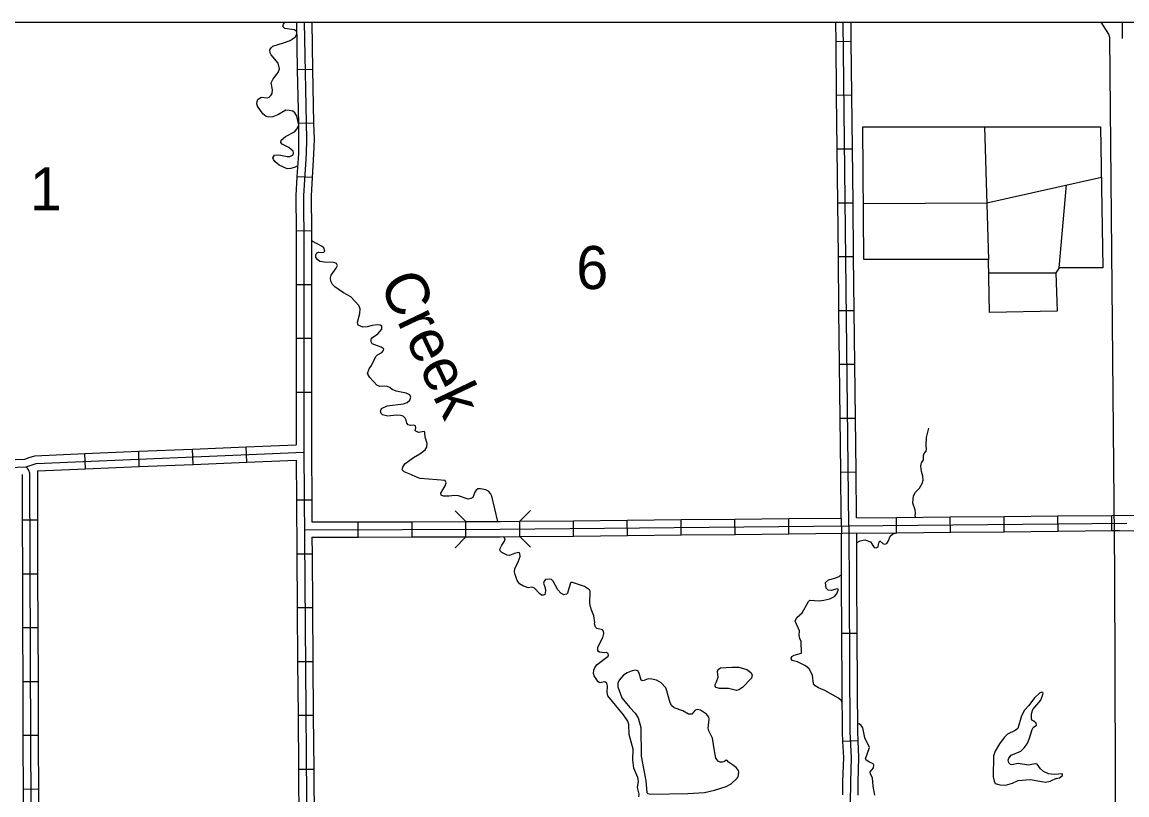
# Model space of a CAD drawing. Extents: x 982240 to 1103002, y 974866 to 1054902.
# Drawn here: x 1046772 to 1057609, y 1010471 to 1018049 of the extents above; entities that cross this region are included whole.
import ezdxf

# ---------------------------------------------------------------- set-up
doc = ezdxf.new("R2010")
doc.units = 0
for name, color, linetype in [('10', 7, 'Continuous'), ('32', 7, 'Continuous'), ('35', 7, 'Continuous'), ('38', 7, 'Continuous'), ('45', 7, 'Continuous'), ('5', 7, 'Continuous'), ('R_Draft', 7, 'Continuous')]:
    doc.layers.add(name, color=color, linetype=linetype)

msp = doc.modelspace()

# ---------------------------------------------------------------- linework, layer by layer
at = {"layer": '10'}
msp.add_lwpolyline([(1057522, 1006715), (1057508, 1007730), (1057491, 1012652), (1057441, 1017898), (1057431, 1017930), (1057357, 1018049)], dxfattribs=at)
at = {"layer": '32'}
for p, q in [((1054756, 1017860), (1054754, 1018049)), ((1054906, 1017862), (1054904, 1018049)), ((1054756, 1017860), (1054906, 1017862)), ((1049622, 1017585), (1049472, 1017582)), ((1054761, 1017332), (1054911, 1017334)), ((1049632, 1017057), (1049482, 1017054)), ((1054767, 1016805), (1054917, 1016806)), ((1049618, 1016524), (1049468, 1016533)), ((1054773, 1016277), (1054923, 1016278)), ((1049610, 1016001), (1049460, 1016000)), ((1054779, 1015749), (1054929, 1015750)), ((1049611, 1015473), (1049461, 1015473)), ((1054785, 1015221), (1054935, 1015222)), ((1049611, 1014945), (1049461, 1014945)), ((1054791, 1014693), (1054941, 1014694)), ((1049610, 1014417), (1049460, 1014417)), ((1049460, 1014417), (1049460, 1013905)), ((1054796, 1014165), (1054946, 1014166)), ((1048971, 1013884), (1049460, 1013905)), ((1047395, 1013668), (1047389, 1013818)), ((1047922, 1013690), (1047916, 1013840)), ((1048450, 1013712), (1048444, 1013862)), ((1048978, 1013734), (1048971, 1013884)), ((1048978, 1013734), (1049461, 1013754)), ((1049461, 1013754), (1049463, 1013360)), ((1046772, 1013612), (1046773, 1013168)), ((1046922, 1013648), (1047395, 1013668)), ((1046922, 1013648), (1046923, 1013168)), ((1054802, 1013637), (1054952, 1013638)), ((1054807, 1013186), (1054802, 1013637)), ((1054957, 1013187), (1054952, 1013638)), ((1049613, 1013361), (1049463, 1013360)), ((1046773, 1013168), (1046923, 1013168)), ((1050070, 1012999), (1050069, 1013149)), ((1050598, 1013000), (1050597, 1013150)), ((1051126, 1013001), (1051125, 1013151)), ((1051654, 1013004), (1051653, 1013154)), ((1052182, 1013009), (1052181, 1013159)), ((1052710, 1013015), (1052709, 1013165)), ((1053238, 1013020), (1053237, 1013170)), ((1053766, 1013025), (1053765, 1013175)), ((1054293, 1013180), (1054807, 1013186)), ((1054294, 1013030), (1054293, 1013180)), ((1054813, 1013030), (1054811, 1013180)), ((1054957, 1013187), (1055349, 1013191)), ((1055350, 1013041), (1055349, 1013191)), ((1055878, 1013046), (1055877, 1013196)), ((1056406, 1013051), (1056405, 1013201)), ((1056934, 1013057), (1056933, 1013207)), ((1057462, 1013062), (1057461, 1013212)), ((1049617, 1012833), (1049467, 1012832)), ((1046775, 1012640), (1046925, 1012640)), ((1049621, 1012305), (1049471, 1012304)), ((1046777, 1012112), (1046927, 1012112)), ((1049625, 1011777), (1049475, 1011776)), ((1046779, 1011584), (1046929, 1011584)), ((1049629, 1011249), (1049479, 1011248)), ((1046781, 1011056), (1046931, 1011056)), ((1049633, 1010721), (1049483, 1010720)), ((1046784, 1010528), (1046934, 1010529))]:
    msp.add_line(p, q, dxfattribs=at)
for points in [[(1049463, 1018049), (1049472, 1017582)], [(1049540, 1018049), (1049562, 1016898), (1049558, 1016757), (1049533, 1016348), (1049537, 1015835), (1049536, 1013831), (1049577, 1008327), (1049592, 1007765), (1049585, 1007779), (1049616, 1001142)], [(1049613, 1018049), (1049622, 1017585)], [(1054882, 1013110), (1054827, 1018049)], [(1057567, 1017887), (1057565, 1018049)], [(1054761, 1017332), (1054756, 1017860)], [(1054911, 1017334), (1054906, 1017862)], [(1049472, 1017582), (1049482, 1017054)], [(1049622, 1017585), (1049632, 1017057)], [(1054767, 1016805), (1054761, 1017332)], [(1054917, 1016806), (1054911, 1017334)], [(1049482, 1017054), (1049485, 1016899), (1049482, 1016760), (1049468, 1016533)], [(1049632, 1017057), (1049636, 1016898), (1049632, 1016753), (1049618, 1016524)], [(1054773, 1016277), (1054767, 1016805)], [(1054923, 1016278), (1054917, 1016806)], [(1049468, 1016533), (1049457, 1016350), (1049460, 1016000)], [(1049618, 1016524), (1049607, 1016346), (1049610, 1016001)], [(1054779, 1015749), (1054773, 1016277)], [(1054929, 1015750), (1054923, 1016278)], [(1049460, 1016000), (1049461, 1015835), (1049461, 1015473)], [(1049610, 1016001), (1049611, 1015835), (1049611, 1015473)], [(1054785, 1015221), (1054779, 1015749)], [(1054935, 1015222), (1054929, 1015750)], [(1049461, 1015473), (1049461, 1014945)], [(1049611, 1015473), (1049611, 1014945)], [(1054791, 1014693), (1054785, 1015221)], [(1054941, 1014694), (1054935, 1015222)], [(1049461, 1014945), (1049460, 1014417)], [(1049611, 1014945), (1049610, 1014417)], [(1054796, 1014165), (1054791, 1014693)], [(1054946, 1014166), (1054941, 1014694)], [(1049610, 1014417), (1049610, 1013889)], [(1054802, 1013637), (1054796, 1014165)], [(1054952, 1013638), (1054946, 1014166)], [(1044148, 1013587), (1046814, 1013688), (1046911, 1013721), (1049536, 1013831)], [(1046842, 1013778), (1046897, 1013797), (1047389, 1013818)], [(1047389, 1013818), (1047916, 1013840)], [(1047916, 1013840), (1048444, 1013862)], [(1048444, 1013862), (1048971, 1013884)], [(1049610, 1013889), (1049610, 1013832), (1049613, 1013361)], [(1046339, 1013746), (1046800, 1013764), (1046842, 1013778)], [(1046814, 1013688), (1046836, 1013656), (1046845, 1013628), (1046855, 1010971), (1046871, 1008241)], [(1047395, 1013668), (1047922, 1013690)], [(1047922, 1013690), (1048450, 1013712)], [(1048450, 1013712), (1048978, 1013734)], [(1049463, 1013360), (1049467, 1012832)], [(1049613, 1013361), (1049615, 1013148)], [(1046773, 1013168), (1046775, 1012640)], [(1046923, 1013168), (1046925, 1012640)], [(1049542, 1013071), (1051463, 1013076), (1057609, 1013137)], [(1049615, 1013148), (1050069, 1013149)], [(1050069, 1013149), (1050597, 1013150)], [(1050597, 1013150), (1051125, 1013151)], [(1051125, 1013151), (1051462, 1013152), (1051653, 1013154)], [(1051653, 1013154), (1052181, 1013159)], [(1052181, 1013159), (1052709, 1013165)], [(1052709, 1013165), (1053237, 1013170)], [(1053237, 1013170), (1053765, 1013175)], [(1053765, 1013175), (1054293, 1013180)], [(1055349, 1013191), (1055877, 1013196)], [(1055877, 1013196), (1056405, 1013201)], [(1056405, 1013201), (1056933, 1013207)], [(1056933, 1013207), (1057461, 1013212)], [(1057461, 1013212), (1057685, 1013214), (1057972, 1013210)], [(1053238, 1013020), (1053766, 1013025)], [(1053766, 1013025), (1054294, 1013030)], [(1054294, 1013030), (1054822, 1013036)], [(1054822, 1013036), (1055350, 1013041)], [(1055350, 1013041), (1055878, 1013046)], [(1055878, 1013046), (1056406, 1013051)], [(1056406, 1013051), (1056934, 1013057)], [(1056934, 1013057), (1057462, 1013062)], [(1057462, 1013062), (1057536, 1013063), (1057977, 1013060)], [(1049616, 1012998), (1050070, 1012999)], [(1049616, 1012998), (1049617, 1012833)], [(1050070, 1012999), (1050598, 1013000)], [(1050598, 1013000), (1051126, 1013001)], [(1051126, 1013001), (1051463, 1013002), (1051654, 1013004)], [(1051654, 1013004), (1052182, 1013009)], [(1052182, 1013009), (1052710, 1013015)], [(1052710, 1013015), (1053238, 1013020)], [(1049467, 1012832), (1049471, 1012304)], [(1049617, 1012833), (1049621, 1012305)], [(1046775, 1012640), (1046777, 1012112)], [(1046925, 1012640), (1046927, 1012112)], [(1049471, 1012304), (1049475, 1011776)], [(1049621, 1012305), (1049625, 1011777)], [(1046777, 1012112), (1046779, 1011584)], [(1046927, 1012112), (1046929, 1011584)], [(1049475, 1011776), (1049479, 1011248)], [(1049625, 1011777), (1049629, 1011249)], [(1046779, 1011584), (1046781, 1011056)], [(1046929, 1011584), (1046931, 1011056)], [(1049479, 1011248), (1049483, 1010720)], [(1049629, 1011249), (1049633, 1010721)], [(1046781, 1011056), (1046781, 1010970), (1046784, 1010528)], [(1046931, 1011056), (1046931, 1010971), (1046934, 1010529)], [(1049483, 1010720), (1049487, 1010192)], [(1049633, 1010721), (1049637, 1010193)], [(1046784, 1010528), (1046787, 1010000)], [(1046934, 1010529), (1046937, 1010001)]]:
    msp.add_lwpolyline(points, dxfattribs=at)
at = {"layer": '35'}
for points in [[(1049466, 1017956), (1049441, 1017974), (1049350, 1017986), (1049330, 1018005), (1049335, 1018030), (1049351, 1018049)], [(1049214, 1017798), (1049231, 1017814), (1049336, 1017844), (1049403, 1017869), (1049452, 1017902), (1049467, 1017930)], [(1049473, 1016640), (1049451, 1016626), (1049410, 1016613), (1049371, 1016611), (1049293, 1016645), (1049255, 1016678), (1049239, 1016701), (1049233, 1016718), (1049248, 1016743), (1049291, 1016747), (1049372, 1016732), (1049400, 1016732), (1049430, 1016747), (1049434, 1016764), (1049430, 1016783), (1049413, 1016801), (1049388, 1016818), (1049322, 1016851), (1049309, 1016869), (1049314, 1016892), (1049355, 1016926), (1049443, 1016974), (1049463, 1016997), (1049486, 1017039), (1049474, 1017100), (1049464, 1017132), (1049449, 1017160), (1049427, 1017174), (1049393, 1017182), (1049360, 1017184), (1049282, 1017139), (1049231, 1017120), (1049191, 1017116), (1049165, 1017124), (1049134, 1017148), (1049081, 1017223), (1049074, 1017247), (1049077, 1017271), (1049085, 1017290), (1049118, 1017313), (1049178, 1017307), (1049195, 1017313), (1049212, 1017328), (1049226, 1017349), (1049228, 1017383), (1049217, 1017454), (1049235, 1017494), (1049284, 1017556), (1049297, 1017589), (1049284, 1017646), (1049214, 1017727), (1049206, 1017748), (1049204, 1017778), (1049214, 1017798)], [(1055019, 1017023), (1057351, 1017023)], [(1055029, 1015720), (1055019, 1017023)], [(1056211, 1017023), (1056253, 1015720)], [(1057351, 1017023), (1057372, 1015640)], [(1055024, 1016271), (1056235, 1016275), (1057359, 1016529)], [(1056946, 1015640), (1057018, 1016452)], [(1049796, 1015542), (1049805, 1015568), (1049854, 1015635), (1049865, 1015661), (1049857, 1015682), (1049831, 1015692), (1049738, 1015695), (1049692, 1015702), (1049672, 1015717), (1049655, 1015742), (1049653, 1015765), (1049664, 1015787), (1049683, 1015793), (1049716, 1015789), (1049732, 1015792), (1049742, 1015803), (1049733, 1015834), (1049716, 1015847), (1049618, 1015899), (1049608, 1015907)], [(1057372, 1015640), (1056946, 1015640), (1056913, 1015589), (1056925, 1015215), (1056261, 1015202), (1056253, 1015720), (1055029, 1015720)], [(1050881, 1013430), (1050922, 1013503), (1050932, 1013532), (1050921, 1013554), (1050676, 1013575), (1050642, 1013587), (1050585, 1013612), (1050519, 1013640), (1050502, 1013660), (1050506, 1013685), (1050528, 1013717), (1050612, 1013779), (1050675, 1013815), (1050726, 1013853), (1050741, 1013881), (1050745, 1013915), (1050725, 1013978), (1050724, 1014028), (1050715, 1014034), (1050661, 1014023), (1050627, 1014041), (1050634, 1014070), (1050632, 1014091), (1050610, 1014098), (1050582, 1014094), (1050558, 1014100), (1050545, 1014116), (1050539, 1014146), (1050529, 1014165), (1050511, 1014183), (1050484, 1014192), (1050442, 1014193), (1050359, 1014183), (1050307, 1014197), (1050293, 1014212), (1050287, 1014234), (1050297, 1014259), (1050353, 1014285), (1050514, 1014305), (1050548, 1014320), (1050577, 1014342), (1050585, 1014370), (1050577, 1014393), (1050540, 1014409), (1050440, 1014429), (1050401, 1014446), (1050379, 1014467), (1050347, 1014480), (1050282, 1014474), (1050252, 1014490), (1050183, 1014563), (1050162, 1014603), (1050177, 1014649), (1050200, 1014681), (1050242, 1014769), (1050259, 1014787), (1050302, 1014809), (1050314, 1014824), (1050319, 1014840), (1050312, 1014852), (1050296, 1014862), (1050205, 1014894), (1050195, 1014912), (1050196, 1014939), (1050210, 1014957), (1050262, 1014993), (1050302, 1015038), (1050301, 1015066), (1050284, 1015078), (1050256, 1015080), (1050206, 1015074), (1050156, 1015059), (1050114, 1015058), (1050068, 1015078), (1050063, 1015107), (1050085, 1015191), (1050089, 1015237), (1050075, 1015270), (1049996, 1015355), (1049926, 1015393), (1049841, 1015454), (1049817, 1015477), (1049801, 1015508), (1049796, 1015542)], [(1056255, 1015589), (1056913, 1015589)], [(1055587, 1013694), (1055595, 1013726), (1055614, 1013757), (1055615, 1013799), (1055621, 1013819), (1055639, 1013840), (1055643, 1013863), (1055640, 1013895), (1055645, 1013975), (1055666, 1014066)], [(1055535, 1013195), (1055533, 1013209), (1055537, 1013233), (1055533, 1013267), (1055510, 1013331), (1055517, 1013402), (1055536, 1013439), (1055574, 1013480), (1055601, 1013524), (1055610, 1013557), (1055608, 1013596), (1055594, 1013643), (1055587, 1013694)], [(1051440, 1013152), (1051381, 1013400), (1051368, 1013427), (1051346, 1013450), (1051320, 1013461), (1051268, 1013473), (1051244, 1013471), (1051225, 1013459), (1051213, 1013440), (1051192, 1013388), (1051174, 1013377), (1051147, 1013372), (1051053, 1013403), (1051015, 1013408), (1050961, 1013400), (1050905, 1013401), (1050884, 1013410), (1050881, 1013430)], [(1054956, 1012942), (1054992, 1012963), (1055040, 1012972), (1055094, 1012953), (1055130, 1012897), (1055149, 1012894), (1055170, 1012904), (1055176, 1012943), (1055185, 1012962), (1055214, 1012936), (1055232, 1012928), (1055255, 1012937), (1055272, 1012962), (1055288, 1013007), (1055313, 1013030), (1055353, 1013040)], [(1052523, 1011840), (1052520, 1011855), (1052506, 1011866), (1052481, 1011863), (1052437, 1011869), (1052419, 1011880), (1052420, 1011918), (1052469, 1012015), (1052480, 1012055), (1052476, 1012075), (1052467, 1012090), (1052409, 1012101), (1052397, 1012114), (1052388, 1012147), (1052390, 1012162), (1052379, 1012228), (1052353, 1012291), (1052342, 1012349), (1052345, 1012468), (1052338, 1012483), (1052289, 1012513), (1052172, 1012555), (1052159, 1012555), (1052153, 1012549), (1052123, 1012449), (1052111, 1012439), (1052087, 1012433), (1052056, 1012448), (1052028, 1012482), (1051982, 1012567), (1051965, 1012582), (1051942, 1012587), (1051905, 1012582), (1051893, 1012568), (1051886, 1012548), (1051904, 1012500), (1051908, 1012471), (1051900, 1012433), (1051887, 1012428), (1051868, 1012430), (1051851, 1012441), (1051800, 1012499), (1051771, 1012507), (1051737, 1012502), (1051685, 1012520), (1051651, 1012542), (1051629, 1012573), (1051608, 1012633), (1051603, 1012659), (1051604, 1012686), (1051639, 1012755), (1051658, 1012807), (1051655, 1012840), (1051642, 1012849), (1051603, 1012839), (1051552, 1012818), (1051530, 1012821), (1051477, 1012848), (1051461, 1012865), (1051458, 1012880), (1051477, 1012921), (1051505, 1012960), (1051510, 1012981), (1051499, 1013002)], [(1054551, 1011539), (1054536, 1011560), (1054525, 1011646), (1054491, 1011707), (1054456, 1011736), (1054378, 1011775), (1054326, 1011789), (1054317, 1011804), (1054321, 1011828), (1054345, 1011842), (1054418, 1011862), (1054414, 1011975), (1054401, 1012004), (1054396, 1012034), (1054398, 1012080), (1054355, 1012175), (1054373, 1012210), (1054423, 1012256), (1054485, 1012366), (1054498, 1012380), (1054590, 1012374), (1054637, 1012379), (1054695, 1012393), (1054740, 1012415), (1054761, 1012438), (1054780, 1012485), (1054768, 1012492), (1054707, 1012476), (1054678, 1012479), (1054659, 1012498), (1054654, 1012554), (1054681, 1012580), (1054745, 1012595), (1054786, 1012612), (1054799, 1012625)], [(1052822, 1010451), (1052824, 1010478), (1052808, 1010544), (1052817, 1010606), (1052813, 1010643), (1052774, 1010734), (1052762, 1010811), (1052765, 1010918), (1052727, 1011063), (1052725, 1011160), (1052715, 1011193), (1052671, 1011256), (1052518, 1011443), (1052512, 1011476), (1052516, 1011541), (1052509, 1011567), (1052490, 1011580), (1052438, 1011570), (1052422, 1011580), (1052385, 1011638), (1052378, 1011662), (1052380, 1011694), (1052391, 1011719), (1052414, 1011749), (1052521, 1011832), (1052523, 1011840)], [(1053863, 1011548), (1053839, 1011525), (1053803, 1011500), (1053781, 1011496), (1053703, 1011514), (1053614, 1011515), (1053582, 1011523), (1053569, 1011537), (1053569, 1011552), (1053583, 1011579), (1053600, 1011625), (1053595, 1011680), (1053600, 1011701), (1053623, 1011717), (1053735, 1011725), (1053803, 1011722), (1053882, 1011701), (1053920, 1011671), (1053932, 1011647), (1053927, 1011616), (1053901, 1011589)], [(1053700, 1010791), (1053689, 1010808), (1053677, 1010811), (1053661, 1010798), (1053639, 1010792), (1053619, 1010792), (1053600, 1010803), (1053576, 1010832), (1053564, 1010902), (1053544, 1011026), (1053509, 1011100), (1053503, 1011124), (1053513, 1011214), (1053509, 1011232), (1053485, 1011264), (1053428, 1011301), (1053397, 1011309), (1053375, 1011302), (1053342, 1011261), (1053309, 1011262), (1053253, 1011294), (1053169, 1011324), (1053147, 1011343), (1053129, 1011373), (1053097, 1011491), (1053088, 1011521), (1053041, 1011569), (1052996, 1011596), (1052951, 1011606), (1052912, 1011608), (1052863, 1011591), (1052845, 1011596), (1052825, 1011665), (1052811, 1011687), (1052788, 1011693), (1052756, 1011689), (1052706, 1011668), (1052671, 1011644), (1052629, 1011597), (1052616, 1011566), (1052616, 1011529), (1052654, 1011422), (1052732, 1011328), (1052786, 1011273), (1052815, 1011225), (1052841, 1011133), (1052844, 1010851), (1052892, 1010610), (1052899, 1010494), (1052910, 1010484), (1052938, 1010478)], [(1053901, 1011589), (1053863, 1011548)], [(1054814, 1011383), (1054806, 1011397), (1054781, 1011418), (1054645, 1011496), (1054585, 1011520), (1054551, 1011539)], [(1056916, 1010631), (1056949, 1010639), (1056979, 1010661), (1056977, 1010676), (1056899, 1010672), (1056840, 1010679), (1056792, 1010701), (1056762, 1010727), (1056730, 1010771), (1056709, 1010777), (1056644, 1010762), (1056544, 1010778), (1056479, 1010765), (1056466, 1010770), (1056451, 1010786), (1056446, 1010811), (1056452, 1010832), (1056475, 1010860), (1056569, 1010900), (1056603, 1010932), (1056631, 1010973), (1056651, 1011017), (1056681, 1011111), (1056691, 1011132), (1056723, 1011156), (1056719, 1011174), (1056697, 1011194), (1056682, 1011200), (1056673, 1011213), (1056674, 1011267), (1056687, 1011307), (1056765, 1011400), (1056785, 1011456), (1056787, 1011469), (1056784, 1011476), (1056772, 1011477), (1056752, 1011470), (1056702, 1011422), (1056646, 1011346), (1056604, 1011301), (1056575, 1011246), (1056541, 1011122), (1056512, 1011101), (1056438, 1011065), (1056404, 1011035), (1056358, 1010973), (1056318, 1010900), (1056300, 1010855), (1056298, 1010649), (1056307, 1010604), (1056318, 1010582), (1056363, 1010569), (1056417, 1010566), (1056488, 1010587), (1056542, 1010613), (1056661, 1010623), (1056754, 1010605), (1056806, 1010595)], [(1055136, 1010467), (1055121, 1010555), (1055114, 1010638), (1055094, 1010674), (1055092, 1010696), (1055124, 1010737), (1055127, 1010761), (1055121, 1010776), (1055084, 1010792), (1055053, 1010813), (1055046, 1010826), (1055086, 1010937), (1055038, 1011031), (1055018, 1011129), (1055004, 1011153), (1054983, 1011167), (1054968, 1011165)], [(1052938, 1010478), (1053303, 1010484), (1053465, 1010495), (1053565, 1010516), (1053678, 1010553), (1053726, 1010580), (1053788, 1010636), (1053795, 1010649), (1053803, 1010694), (1053798, 1010711), (1053776, 1010740), (1053752, 1010759), (1053700, 1010791)], [(1056806, 1010595), (1056859, 1010607)], [(1056916, 1010631), (1056859, 1010607)]]:
    msp.add_lwpolyline(points, dxfattribs=at)
at = {"layer": '38'}
for points in [[(1051019, 1013257), (1051125, 1013151)], [(1051653, 1013154), (1051758, 1013261)], [(1051126, 1013001), (1051021, 1012895)], [(1051760, 1012899), (1051654, 1013004)]]:
    msp.add_lwpolyline(points, dxfattribs=at)
at = {"layer": '45'}
for p, q in [((1054806, 1013036), (1054808, 1012581)), ((1054956, 1013037), (1054958, 1012582)), ((1054961, 1012054), (1054811, 1012053)), ((1054970, 1011001), (1054820, 1010994))]:
    msp.add_line(p, q, dxfattribs=at)
for points in [[(1054882, 1013110), (1054892, 1011089), (1054904, 1010837), (1054897, 1010600), (1054889, 1009962), (1054903, 1009133)], [(1054808, 1012581), (1054811, 1012053)], [(1054958, 1012582), (1054961, 1012054)], [(1054811, 1012053), (1054813, 1011525)], [(1054961, 1012054), (1054963, 1011526)], [(1054813, 1011525), (1054816, 1011087), (1054820, 1010994)], [(1054963, 1011526), (1054966, 1011091), (1054970, 1011001)], [(1054820, 1010994), (1054828, 1010837), (1054821, 1010602), (1054819, 1010471)], [(1054970, 1011001), (1054978, 1010838), (1054970, 1010598), (1054969, 1010469)]]:
    msp.add_lwpolyline(points, dxfattribs=at)
at = {"layer": 'R_Draft'}
msp.add_lwpolyline([(1018617, 1018049), (1063840, 1018049), (1063840, 987556), (1018617, 987556)], close=True, dxfattribs=at)
msp.add_lwpolyline([(1018617, 1018049), (1063840, 1018049), (1063840, 987556), (1018617, 987556)], close=True, dxfattribs=at)

# ---------------------------------------------------------------- texts
at = {"layer": '35'}
msp.add_text('Creek', height=422.4, rotation=295.4835, dxfattribs=at).set_placement((1050270, 1015489))
at = {"layer": '5'}
for s, p in [('1', (1046849, 1016203)), ('6', (1052208, 1015431))]:
    msp.add_text(s, height=422, dxfattribs=at).set_placement(p)

doc.saveas('drawing.dxf')
